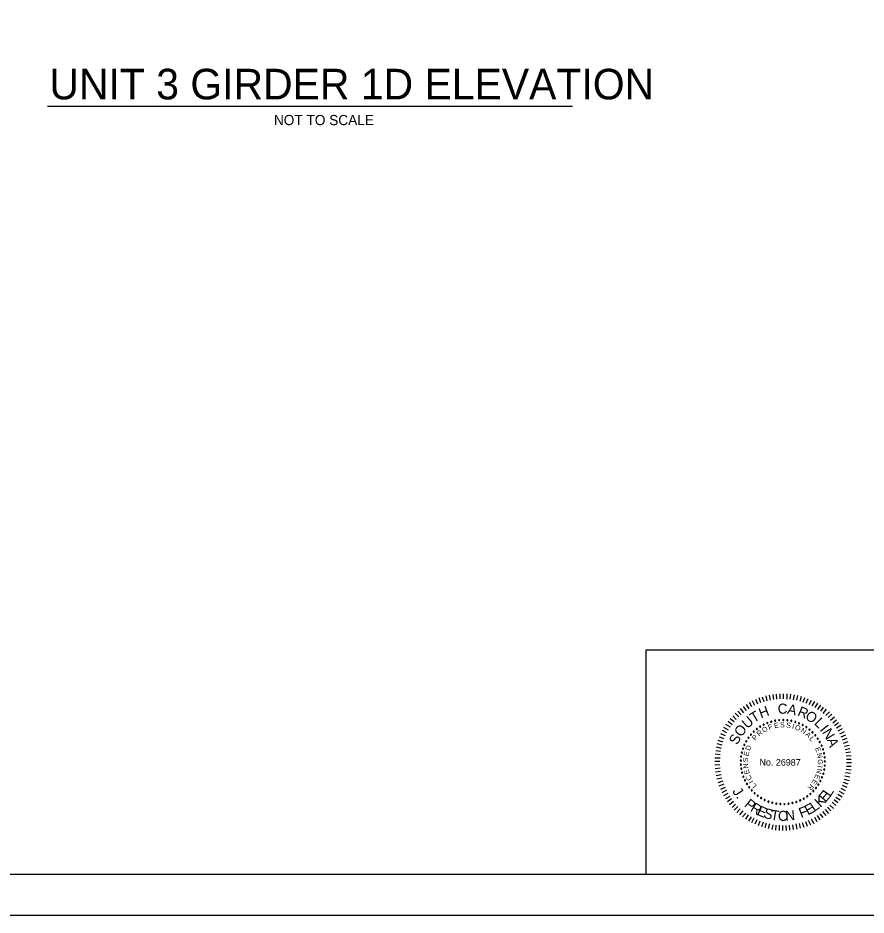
# Model space of a CAD drawing. Extents: x -305 to -161, y -187 to -99.
# Drawn here: x -245.45 to -203.87, y -187.49 to -143.49 of the extents above; entities that cross this region are included whole.
import ezdxf

# ---------------------------------------------------------------- set-up
doc = ezdxf.new("R2010")
doc.units = 0
for name, color, linetype in [('BR_BORDER LINES', 7, 'Continuous'), ('BR_TEXT', 7, 'Continuous'), ('Level 31', 7, 'Continuous')]:
    doc.layers.add(name, color=color, linetype=linetype)

msp = doc.modelspace()

# ---------------------------------------------------------------- linework, layer by layer
at = {"layer": 'BR_BORDER LINES'}
for p, q in [((-214.64, -174.489), (-193.18, -174.489)), ((-214.64, -185.489), (-214.64, -174.489)), ((-297.843, -185.489), (-163.178, -185.489))]:
    msp.add_line(p, q, dxfattribs=at)
at = {"layer": 'BR_TEXT'}
for p, q in [((-244.003, -147.82), (-218.256, -147.82)), ((-209.02, -177.076), (-209.103, -176.842)), ((-208.861, -177.026), (-208.949, -176.795)), ((-208.717, -176.986), (-208.77, -176.742)), ((-208.552, -176.946), (-208.608, -176.709)), ((-208.394, -176.917), (-208.429, -176.673)), ((-208.236, -176.901), (-208.251, -176.657)), ((-208.077, -176.892), (-208.075, -176.634)), ((-207.909, -176.883), (-207.907, -176.636)), ((-207.741, -176.895), (-207.732, -176.637)), ((-207.58, -176.906), (-207.561, -176.663)), ((-207.426, -176.925), (-207.382, -176.681)), ((-207.265, -176.957), (-207.208, -176.721)), ((-207.1, -176.999), (-207.036, -176.756)), ((-206.953, -177.042), (-206.865, -176.813)), ((-206.795, -177.095), (-206.708, -176.862)), ((-209.726, -177.462), (-209.883, -177.258)), ((-209.602, -177.377), (-209.724, -177.16)), ((-209.461, -177.282), (-209.582, -177.065)), ((-209.323, -177.211), (-209.427, -176.987)), ((-209.175, -177.144), (-209.269, -176.92)), ((-206.652, -177.165), (-206.54, -176.942)), ((-206.508, -177.234), (-206.383, -177.012)), ((-206.358, -177.308), (-206.229, -177.093)), ((-206.225, -177.405), (-206.089, -177.19)), ((-206.091, -177.492), (-205.946, -177.291)), ((-210.228, -177.894), (-210.402, -177.724)), ((-210.11, -177.771), (-210.287, -177.594)), ((-209.993, -177.662), (-210.159, -177.482)), ((-209.861, -177.564), (-210.021, -177.363)), ((-205.962, -177.596), (-205.799, -177.398)), ((-205.836, -177.696), (-205.663, -177.519)), ((-205.723, -177.807), (-205.55, -177.634)), ((-210.519, -178.269), (-210.735, -178.137)), ((-210.432, -178.153), (-210.63, -177.993)), ((-210.328, -178.02), (-210.526, -177.864)), ((-205.611, -177.932), (-205.421, -177.765)), ((-205.502, -178.06), (-205.316, -177.907)), ((-205.407, -178.194), (-205.21, -178.038)), ((-205.319, -178.312), (-205.109, -178.183)), ((-210.756, -178.699), (-210.985, -178.598)), ((-210.686, -178.552), (-210.912, -178.441)), ((-210.617, -178.416), (-210.832, -178.287)), ((-205.231, -178.46), (-205.017, -178.335)), ((-205.16, -178.598), (-204.929, -178.49)), ((-210.876, -179.014), (-211.122, -178.923)), ((-210.826, -178.853), (-211.059, -178.766)), ((-205.089, -178.746), (-204.862, -178.648)), ((-205.022, -178.901), (-204.795, -178.817)), ((-204.968, -179.063), (-204.738, -178.976)), ((-210.996, -179.47), (-211.24, -179.437)), ((-210.954, -179.326), (-211.204, -179.262)), ((-210.925, -179.158), (-211.168, -179.098)), ((-204.928, -179.207), (-204.688, -179.151)), ((-204.895, -179.376), (-204.654, -179.316)), ((-204.862, -179.52), (-204.625, -179.491)), ((-211.034, -179.957), (-211.285, -179.955)), ((-211.026, -179.792), (-211.284, -179.79)), ((-211.015, -179.634), (-211.261, -179.605)), ((-204.836, -179.685), (-204.592, -179.66)), ((-204.831, -179.843), (-204.59, -179.845)), ((-211.029, -180.129), (-211.286, -180.133)), ((-211.02, -180.283), (-211.267, -180.312)), ((-204.841, -180.334), (-204.598, -180.367)), ((-204.833, -180.18), (-204.593, -180.189)), ((-204.822, -180.008), (-204.578, -180.01)), ((-211.004, -180.448), (-211.248, -180.484)), ((-210.964, -180.606), (-211.215, -180.659)), ((-210.938, -180.775), (-211.182, -180.831)), ((-204.942, -180.824), (-204.702, -180.885)), ((-204.906, -180.656), (-204.666, -180.713)), ((-204.87, -180.499), (-204.634, -180.538)), ((-210.891, -180.923), (-211.139, -181.006)), ((-210.845, -181.077), (-211.079, -181.161)), ((-210.777, -181.226), (-211.008, -181.334)), ((-205.11, -181.272), (-204.884, -181.384)), ((-205.04, -181.125), (-204.814, -181.213)), ((-204.984, -180.971), (-204.755, -181.059)), ((-210.71, -181.37), (-210.937, -181.489)), ((-210.642, -181.519), (-210.859, -181.644)), ((-210.547, -181.667), (-210.765, -181.792)), ((-205.347, -181.71), (-205.139, -181.839)), ((-205.257, -181.563), (-205.045, -181.692)), ((-205.183, -181.416), (-204.954, -181.538)), ((-210.462, -181.784), (-210.663, -181.93)), ((-210.361, -181.919), (-210.561, -182.075)), ((-210.262, -182.054), (-210.439, -182.217)), ((-210.146, -182.158), (-210.326, -182.338)), ((-205.645, -182.092), (-205.458, -182.258)), ((-205.535, -181.959), (-205.351, -182.118)), ((-205.437, -181.826), (-205.243, -181.975)), ((-210.031, -182.279), (-210.2, -182.463)), ((-209.901, -182.383), (-210.064, -182.57)), ((-209.768, -182.487), (-209.928, -182.678)), ((-209.645, -182.574), (-209.77, -182.782)), ((-206.133, -182.517), (-205.99, -182.71)), ((-206.002, -182.415), (-205.842, -182.605)), ((-205.874, -182.313), (-205.704, -182.5)), ((-205.76, -182.194), (-205.589, -182.377)), ((-209.505, -182.664), (-209.63, -182.879)), ((-209.368, -182.744), (-209.477, -182.967)), ((-209.221, -182.814), (-209.319, -183.037)), ((-209.068, -182.884), (-209.155, -183.11)), ((-208.91, -182.933), (-209.001, -183.166)), ((-208.766, -182.983), (-208.823, -183.219)), ((-208.602, -183.011), (-208.662, -183.258)), ((-207.315, -183.022), (-207.262, -183.27)), ((-207.15, -182.996), (-207.09, -183.233)), ((-207.002, -182.949), (-206.918, -183.183)), ((-206.843, -182.902), (-206.759, -183.13)), ((-206.699, -182.835), (-206.591, -183.059)), ((-206.554, -182.768), (-206.432, -182.992)), ((-206.402, -182.69), (-206.277, -182.907)), ((-206.268, -182.602), (-206.135, -182.812)), ((-208.444, -183.057), (-208.484, -183.29)), ((-208.287, -183.076), (-208.306, -183.323)), ((-208.129, -183.087), (-208.131, -183.335)), ((-207.961, -183.099), (-207.963, -183.343)), ((-207.792, -183.09), (-207.787, -183.338)), ((-207.631, -183.081), (-207.616, -183.329)), ((-207.476, -183.065), (-207.437, -183.299))]:
    msp.add_line(p, q, dxfattribs=at)
for centre, start, end in [((-208.887, -178.149), 27.2191, 207.2191), ((-208.887, -178.149), 207.2191, 27.2191), ((-208.706, -178.067), 21.6807, 201.6807), ((-208.706, -178.067), 201.6807, 21.6807), ((-208.517, -178.003), 16.1422, 196.1422), ((-208.517, -178.003), 196.1422, 16.1422), ((-208.323, -177.957), 10.6038, 190.6038), ((-208.323, -177.957), 190.6038, 10.6038), ((-208.126, -177.93), 5.0653, 185.0653), ((-208.126, -177.93), 185.0653, 5.0653), ((-207.926, -177.923), 359.5268, 179.5268), ((-207.926, -177.923), 179.5268, 359.5268), ((-207.727, -177.934), 173.9884, 353.9884), ((-207.727, -177.934), 353.9884, 173.9884), ((-207.531, -177.965), 168.4499, 348.4499), ((-207.531, -177.965), 348.4499, 168.4499), ((-207.338, -178.015), 162.9114, 342.9114), ((-207.338, -178.015), 342.9114, 162.9114), ((-207.15, -178.083), 157.373, 337.373), ((-207.15, -178.083), 337.373, 157.373), ((-206.97, -178.169), 151.8345, 331.8345), ((-206.97, -178.169), 331.8345, 151.8345), ((-209.511, -178.639), 49.373, 229.373), ((-209.511, -178.639), 229.373, 49.373), ((-209.373, -178.495), 43.8345, 223.8345), ((-209.373, -178.495), 223.8345, 43.8345), ((-209.223, -178.364), 38.2961, 218.2961), ((-209.223, -178.364), 218.2961, 38.2961), ((-209.06, -178.248), 32.7576, 212.7576), ((-209.06, -178.248), 212.7576, 32.7576), ((-206.8, -178.272), 146.2961, 326.2961), ((-206.8, -178.272), 326.2961, 146.2961), ((-206.639, -178.39), 140.7576, 320.7576), ((-206.639, -178.39), 320.7576, 140.7576), ((-206.492, -178.524), 135.2191, 315.2191), ((-206.492, -178.524), 315.2191, 135.2191), ((-209.74, -178.964), 60.4499, 240.4499), ((-209.74, -178.964), 240.4499, 60.4499), ((-209.633, -178.796), 54.9114, 234.9114), ((-209.633, -178.796), 234.9114, 54.9114), ((-206.357, -178.671), 129.6807, 309.6807), ((-206.357, -178.671), 309.6807, 129.6807), ((-206.238, -178.831), 124.1422, 304.1422), ((-206.238, -178.831), 304.1422, 124.1422), ((-206.135, -179.001), 118.6038, 298.6038), ((-206.135, -179.001), 298.6038, 118.6038), ((-209.957, -179.52), 77.0653, 257.0653), ((-209.957, -179.52), 257.0653, 77.0653), ((-209.903, -179.328), 71.5268, 251.5268), ((-209.903, -179.328), 251.5268, 71.5268), ((-209.83, -179.142), 65.9884, 245.9884), ((-209.83, -179.142), 245.9884, 65.9884), ((-206.048, -179.181), 113.0653, 293.0653), ((-206.048, -179.181), 293.0653, 113.0653), ((-205.979, -179.368), 107.5268, 287.5268), ((-205.979, -179.368), 287.5268, 107.5268), ((-210.009, -179.914), 88.1422, 268.1422), ((-209.993, -179.716), 82.6038, 262.6038), ((-210.009, -179.914), 268.1422, 88.1422), ((-209.993, -179.716), 262.6038, 82.6038), ((-205.929, -179.561), 101.9884, 281.9884), ((-205.929, -179.561), 281.9884, 101.9884), ((-205.897, -179.758), 96.4499, 276.4499), ((-205.885, -179.957), 90.9114, 270.9114), ((-205.897, -179.758), 276.4499, 96.4499), ((-205.885, -179.957), 270.9114, 90.9114), ((-210.006, -180.114), 93.6807, 273.6807), ((-209.984, -180.312), 99.2191, 279.2191), ((-210.006, -180.114), 273.6807, 93.6807), ((-209.984, -180.312), 279.2191, 99.2191), ((-205.918, -180.353), 79.8345, 259.8345), ((-205.918, -180.353), 259.8345, 79.8345), ((-205.892, -180.156), 85.373, 265.373), ((-205.892, -180.156), 265.373, 85.373), ((-209.943, -180.507), 104.7576, 284.7576), ((-209.943, -180.507), 284.7576, 104.7576), ((-209.884, -180.697), 110.2961, 290.2961), ((-209.884, -180.697), 290.2961, 110.2961), ((-206.026, -180.737), 68.7576, 248.7576), ((-206.026, -180.737), 248.7576, 68.7576), ((-205.963, -180.548), 74.2961, 254.2961), ((-205.963, -180.548), 254.2961, 74.2961), ((-209.806, -180.881), 115.8345, 295.8345), ((-209.806, -180.881), 295.8345, 115.8345), ((-209.711, -181.056), 121.373, 301.373), ((-209.711, -181.056), 301.373, 121.373), ((-209.599, -181.221), 126.9114, 306.9114), ((-209.599, -181.221), 306.9114, 126.9114), ((-206.321, -181.255), 52.1422, 232.1422), ((-206.321, -181.255), 232.1422, 52.1422), ((-206.207, -181.092), 57.6807, 237.6807), ((-206.207, -181.092), 237.6807, 57.6807), ((-206.108, -180.918), 63.2191, 243.2191), ((-206.108, -180.918), 243.2191, 63.2191), ((-209.472, -181.375), 132.4499, 312.4499), ((-209.472, -181.375), 312.4499, 132.4499), ((-209.331, -181.515), 137.9884, 317.9884), ((-209.331, -181.515), 317.9884, 137.9884), ((-209.177, -181.642), 143.5268, 323.5268), ((-209.177, -181.642), 323.5268, 143.5268), ((-206.752, -181.667), 35.5268, 215.5268), ((-206.752, -181.667), 215.5268, 35.5268), ((-206.596, -181.543), 41.0653, 221.0653), ((-206.596, -181.543), 221.0653, 41.0653), ((-206.452, -181.406), 46.6038, 226.6038), ((-206.452, -181.406), 226.6038, 46.6038), ((-209.011, -181.753), 149.0653, 329.0653), ((-209.011, -181.753), 329.0653, 149.0653), ((-208.836, -181.847), 154.6038, 334.6038), ((-208.836, -181.847), 334.6038, 154.6038), ((-208.652, -181.924), 160.1422, 340.1422), ((-208.652, -181.924), 340.1422, 160.1422), ((-208.462, -181.983), 165.6807, 345.6807), ((-208.462, -181.983), 345.6807, 165.6807), ((-208.267, -182.023), 171.2191, 351.2191), ((-208.267, -182.023), 351.2191, 171.2191), ((-208.068, -182.045), 356.7576, 176.7576), ((-208.068, -182.045), 176.7576, 356.7576), ((-207.869, -182.047), 2.2961, 182.2961), ((-207.869, -182.047), 182.2961, 2.2961), ((-207.67, -182.029), 7.8345, 187.8345), ((-207.67, -182.029), 187.8345, 7.8345), ((-207.474, -181.993), 13.373, 193.373), ((-207.474, -181.993), 193.373, 13.373), ((-207.283, -181.938), 18.9114, 198.9114), ((-207.283, -181.938), 198.9114, 18.9114), ((-207.098, -181.865), 24.4499, 204.4499), ((-207.098, -181.865), 204.4499, 24.4499), ((-206.92, -181.774), 29.9884, 209.9884), ((-206.92, -181.774), 209.9884, 29.9884)]:
    msp.add_arc(centre, 0.028, start, end, dxfattribs=at)
at = {"layer": 'Level 31'}
msp.add_lwpolyline([(-305.176, -187.489), (-161.176, -187.489), (-161.176, -99.489), (-305.176, -99.489)], close=True, dxfattribs=at)

# ---------------------------------------------------------------- texts
at = {"layer": 'BR_TEXT'}
for s, height, p in [('UNIT 3 GIRDER 1D ELEVATION', 1.5, (-243.905, -147.483)), ('NOT TO SCALE', 0.5, (-232.898, -148.747))]:
    msp.add_text(s, height=height, dxfattribs=at).set_placement(p)
for s, height, rotation, p in [('H', 0.496, 20.3637, (-209.018, -177.846)), ('C', 0.496, 359.5482, (-208.2, -177.612)), ('A', 0.496, 348.1981, (-207.755, -177.609)), ('R', 0.496, 337.4344, (-207.262, -177.689)), ('U', 0.496, 40.8022, (-209.694, -178.375)), ('T', 0.496, 30.4992, (-209.37, -178.076)), ('O', 0.496, 326.5869, (-206.893, -177.836)), ('O', 0.496, 52.0267, (-209.993, -178.79)), ('F', 0.249, 20.6127, (-208.613, -178.417)), ('E', 0.249, 11.4103, (-208.352, -178.33)), ('S', 0.249, 2.208, (-208.081, -178.286)), ('S', 0.249, 352.6608, (-207.796, -178.287)), ('I', 0.249, 343.1136, (-207.515, -178.335)), ('O', 0.249, 338.4392, (-207.381, -178.376)), ('L', 0.496, 315.9488, (-206.442, -178.107)), ('I', 0.496, 308.6613, (-206.157, -178.404)), ('S', 0.496, 63.2511, (-210.174, -179.173)), ('R', 0.249, 40.3949, (-209.107, -178.737)), ('O', 0.249, 30.8477, (-208.882, -178.561)), ('N', 0.249, 328.2042, (-207.103, -178.501)), ('A', 0.249, 318.657, (-206.867, -178.662)), ('N', 0.496, 300.7037, (-206.035, -178.521)), ('P', 0.249, 49.9421, (-209.299, -178.947)), ('L', 0.249, 309.4546, (-206.668, -178.851)), ('A', 0.496, 289.4792, (-205.798, -178.894)), ('E', 0.249, 78.2388, (-209.633, -179.715)), ('D', 0.249, 69.0364, (-209.567, -179.448)), ('E', 0.249, 291.049, (-206.372, -179.312)), ('S', 0.249, 87.786, (-209.656, -179.999)), ('No. 26987', 0.327, 359.5268, (-209.092, -180.153)), ('N', 0.249, 281.8466, (-206.283, -179.572)), ('G', 0.249, 272.2995, (-206.237, -179.853)), ('N', 0.249, 97.3332, (-209.632, -180.283)), ('E', 0.249, 106.5355, (-209.564, -180.549)), ('N', 0.249, 257.7339, (-206.256, -180.287)), ('I', 0.249, 262.4084, (-206.238, -180.149)), ('C', 0.249, 116.4266, (-209.444, -180.819)), ('E', 0.249, 238.9844, (-206.44, -180.814)), ('E', 0.249, 248.1867, (-206.328, -180.563)), ('J', 0.494, 302.9559, (-210.441, -181.421)), ('I', 0.249, 121.1011, (-209.372, -180.939)), ('L', 0.249, 129.9595, (-209.209, -181.147)), ('R', 0.249, 229.782, (-206.591, -181.044)), ('.', 0.494, 309.3974, (-210.264, -181.693)), ('K', 0.494, 42.3031, (-206.118, -182.229)), ('E', 0.494, 49.3639, (-205.857, -181.989)), ('L', 0.494, 56.4247, (-205.627, -181.718)), ('P', 0.494, 321.1035, (-209.871, -182.13)), ('R', 0.494, 328.5359, (-209.578, -182.362)), ('E', 0.494, 335.9684, (-209.257, -182.555)), ('F', 0.494, 21.1206, (-207.05, -182.735)), ('E', 0.494, 28.1814, (-206.719, -182.605)), ('L', 0.494, 35.2422, (-206.407, -182.436)), ('S', 0.494, 343.0292, (-208.932, -182.698)), ('T', 0.494, 350.4617, (-208.573, -182.804)), ('O', 0.494, 358.1419, (-208.192, -182.863)), ('N', 0.494, 5.8221, (-207.805, -182.872))]:
    msp.add_text(s, height=height, rotation=rotation, dxfattribs=at).set_placement(p)

doc.saveas('drawing.dxf')
